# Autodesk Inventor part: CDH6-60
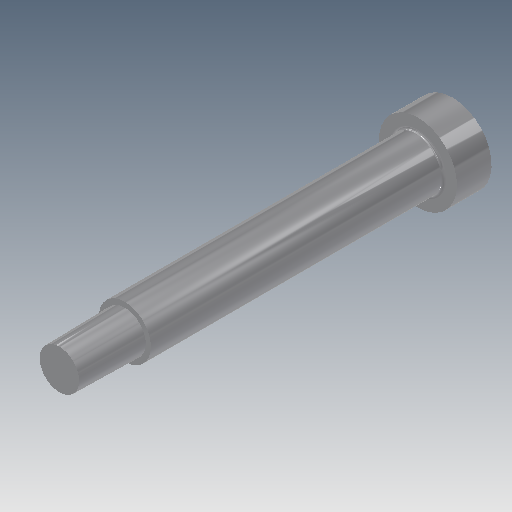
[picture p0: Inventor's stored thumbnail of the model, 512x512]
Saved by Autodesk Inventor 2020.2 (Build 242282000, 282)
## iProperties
Created: 2015-01
Part Number: CDH6-60
Material: Ogólny
Description: Straight Core Pin
Document SubType Name: Modeling
Designer: F.Stasiak
Density: 1 g/cm^3
Appearance: Domyślna
Catalog Web Link: www.expertbooks.pl
Manager: www.cadconsulting.pl
Company: Fabian Stasiak CAD Consulting
Author: F.Stasiak
Subject: Zbiór ćwiczeń. Autodesk Inventor 2020. Kurs Professional
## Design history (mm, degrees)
node "Forma_ZEGAR_260_ZEGAR_260_Rdzeń formujący8_Base"
feature "Solid1::Forma_ZEGAR_260_ZEGAR_260_Rdzeń formujący8_Base"
tag "Bryła wyprowadzona1"
node "Bryła1"
feature "Forma_ZEGAR_260_ZEGAR_260_Rdzeń formujący8_Base_Bodies"
